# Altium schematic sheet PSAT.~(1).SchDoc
size 381 x 241 mm; SheetNumber: 1; SheetTotal: 2
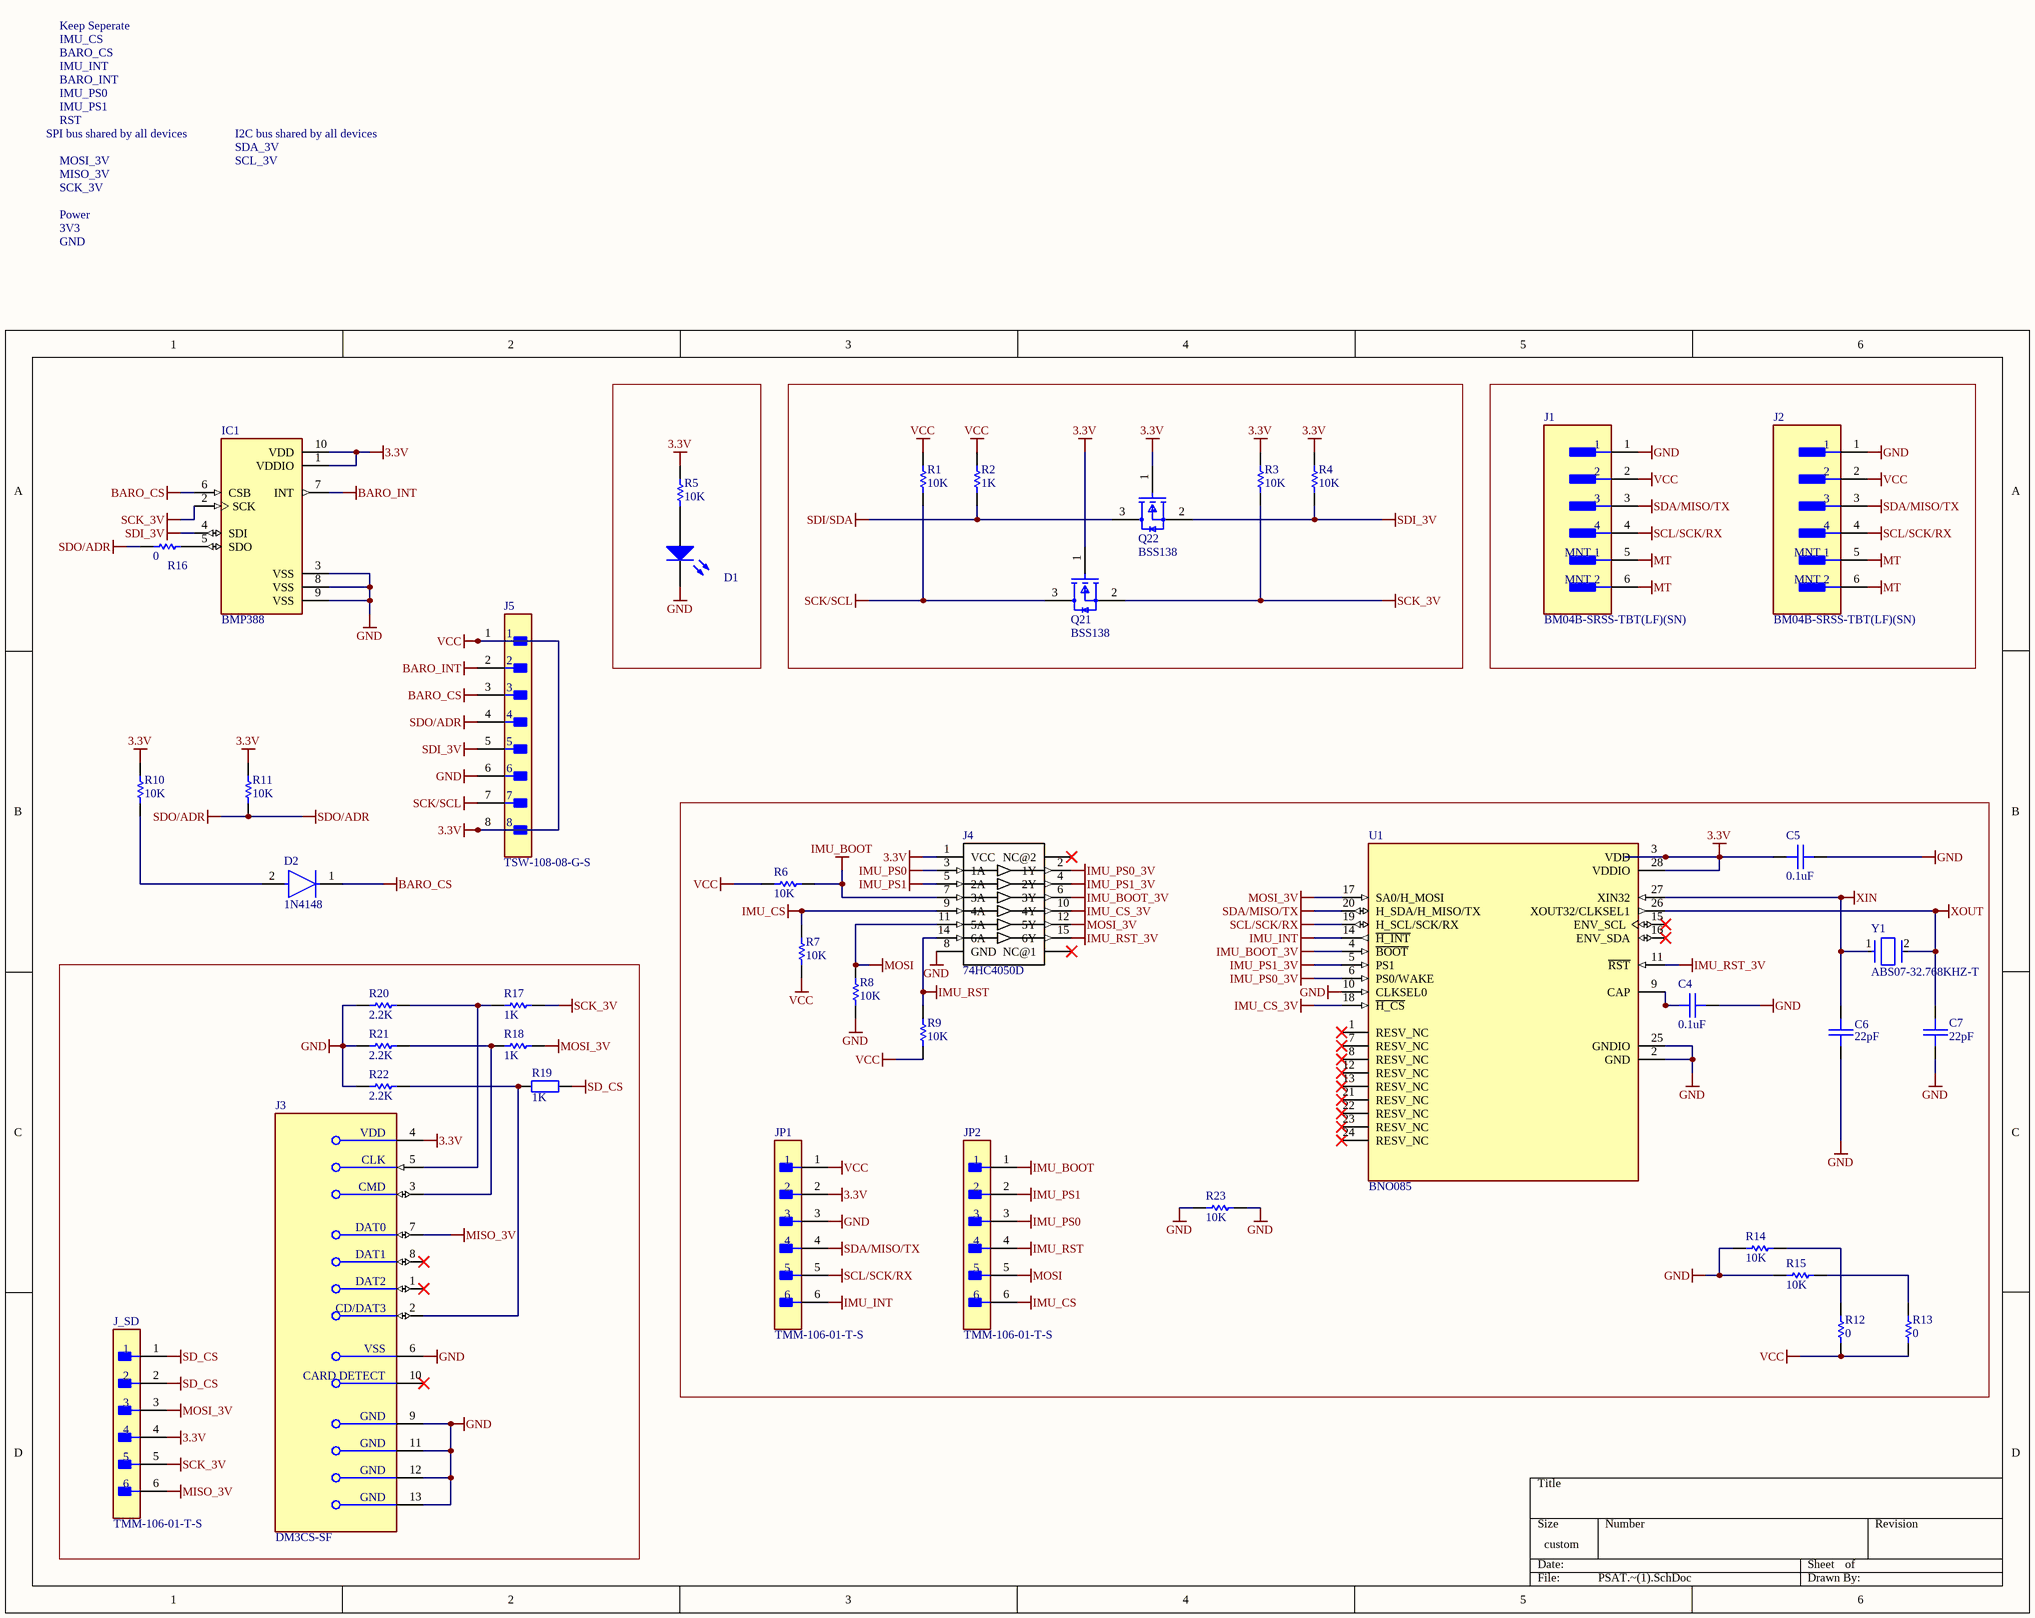
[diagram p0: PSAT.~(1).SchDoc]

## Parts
C4  0.1uF  [0805 CAP]
C5  0.1uF  [0805 CAP]
C6  22pF  [0805 CAP]
C7  22pF  [0805 CAP]
D1  *  [ECE-LED2012-0805SM]  (value not drawn)
D2  1N4148  [FP-017AG-MFG]
IC1  BMP388  [PQFN50P200X200X80-10N]
J1  BM04B-SRSS-TBT(LF)(SN)  [FP-BM04B-SRSS-TBT_LF_SN-MFG]
J2  BM04B-SRSS-TBT(LF)(SN)  [FP-BM04B-SRSS-TBT_LF_SN-MFG]
J3  DM3CS-SF  [FP-DM3CS-SF-MFG]
J4  74HC4050D  [*SO16]
J5  TSW-108-08-G-S  [FP-TSW-108-08-G-S-MFG]
J_SD  TMM-106-01-T-S  [FP-TMM-106-01-T-S-MFG]
JP1  TMM-106-01-T-S  [FP-TMM-106-01-T-S-MFG]
JP2  TMM-106-01-T-S  [FP-TMM-106-01-T-S-MFG]
Q21  BSS138  [FP-318-08-IPC_B]
Q22  BSS138  [FP-318-08-IPC_B]
R1  value 10K  [0805 RES]  (hidden comment: Resistor)
R2  value 1K  [0805 RES]  (hidden comment: Resistor)
R3  value 10K  [0805 RES]  (hidden comment: Resistor)
R4  value 10K  [0805 RES]  (hidden comment: Resistor)
R5  value 10K  [0805 RES]  (hidden comment: Resistor)
R6  value 10K  [0805 RES]  (hidden comment: Resistor)
R7  value 10K  [0805 RES]  (hidden comment: Resistor)
R8  value 10K  [0805 RES]  (hidden comment: Resistor)
R9  value 10K  [0805 RES]  (hidden comment: Resistor)
R10  value 10K  [0805 RES]  (hidden comment: Resistor)
R11  value 10K  [0805 RES]  (hidden comment: Resistor)
R12  value 0  [0805 RES]  (hidden comment: Resistor)
R13  value 0  [0805 RES]  (hidden comment: Resistor)
R14  value 10K  [0805 RES]  (hidden comment: Resistor)
R15  value 10K  [0805 RES]  (hidden comment: Resistor)
R16  value 0  [0805 RES]  (hidden comment: Resistor)
R17  value 1K  [0805 RES]  (hidden comment: Resistor)
R18  value 1K  [0805 RES]  (hidden comment: Resistor)
R19  1K  [0805 RES]
R20  value 2.2K  [0805 RES]  (hidden comment: Resistor)
R21  value 2.2K  [0805 RES]  (hidden comment: Resistor)
R22  value 2.2K  [0805 RES]  (hidden comment: Resistor)
R23  value 10K  [0805 RES]  (hidden comment: Resistor)
U1  BNO085  [IC_BNO085]
Y1  ABS07-32.768KHZ-T  [FP-ABS07-MFG]

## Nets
3.3V: C5.1 IC1.1(VDDIO) IC1.10(VDD) J1.2 J2.2 J3.4(VDD) J4.1(VCC) J5.1 J5.8 J_SD.4 JP1.1 JP1.2 Q21.1(G) Q22.1(G) R1.2 R2.2 R3.2 R4.2 R5.2 R6.1 R7.2 R9.2 R10.2 R11.2 R12.1 R13.1 U1.3(VDD) U1.28(VDDIO)  [also labelled VCC]
BARO_CS: D2.1(C) IC1.6(CSB) J5.3
BARO_INT: IC1.7(INT) J5.2
GND: C4.2 C5.2 C6.2 C7.2 D1.2(K) IC1.3(VSS) IC1.8(VSS) IC1.9(VSS) J1.1 J2.1 J3.6(VSS) J3.9(GND) J3.11(GND) J3.12(GND) J3.13(GND) J4.8(GND) J5.6 JP1.3 R8.2 R14.2 R15.2 R20.1 R21.1 R22.1 R23.1 R23.2 U1.2(GND) U1.10(CLKSEL0) U1.25(GNDIO)
IMU_BOOT: J4.7(3A) JP2.1 R6.2
IMU_BOOT_3V: J4.6(3Y) U1.4(~{BOOT})
IMU_CS: J4.9(4A) JP2.6 R7.1
IMU_CS_3V: J4.10(4Y) U1.18(~{H_CS})
IMU_INT: JP1.6 U1.14(~{H_INT})
IMU_PS0: J4.3(1A) JP2.3
IMU_PS0_3V: J4.2(1Y) U1.6(PS0/WAKE)
IMU_PS1: J4.5(2A) JP2.2
IMU_PS1_3V: J4.4(2Y) U1.5(PS1)
IMU_RST: J4.14(6A) JP2.4 R9.1
IMU_RST_3V: J4.15(6Y) U1.11(~{RST})
MISO_3V: J3.7(DAT0) J_SD.6
MOSI: J4.11(5A) JP2.5 R8.1
MOSI_3V: J4.12(5Y) J_SD.3 R18.2 U1.17(SA0/H_MOSI)
MT: J1.5(MNT_1) J1.6(MNT_2) J2.5(MNT_1) J2.6(MNT_2)
SCK/SCL: J5.7 Q21.3(D) R1.1
SCK_3V: IC1.2(SCK) J_SD.5 Q21.2(S) R3.1 R17.2
SCL/SCK/RX: J1.4 J2.4 JP1.5 U1.19(H_SCL/SCK/RX)
SD_CS: J_SD.1 J_SD.2 R19.2
SDA/MISO/TX: J1.3 J2.3 JP1.4 U1.20(H_SDA/H_MISO/TX)
SDI/SDA: Q22.3(D) R2.1
SDI_3V: IC1.4(SDI) J5.5 Q22.2(S) R4.1
SDO/ADR: J5.4 R11.1 R16.2
XIN: C6.1 U1.27(XIN32) Y1.1
XOUT: C7.1 U1.26(XOUT32/CLKSEL1) Y1.2
NetC4_1: C4.1 U1.9(CAP)
NetD1_1: D1.1(A) R5.1
NetD2_2: D2.2(A) R10.1
NetIC1_5: IC1.5(SDO) R16.1
NetJ3_2: J3.2(CD/DAT3) R19.1 R22.2
NetJ3_3: J3.3(CMD) R18.1 R21.2
NetJ3_5: J3.5(CLK) R17.1 R20.2
NetR12_2: R12.2 R14.1
NetR13_2: R13.2 R15.1

Not connected (* = marked no-connect by the designer): J3 1(DAT2)* 8(DAT1)* 10(CARD_DETECT)*; J4 13(NC@1)* 16(NC@2)*; U1 1(RESV_NC)* 7(RESV_NC)* 8(RESV_NC)* 12(RESV_NC)* 13(RESV_NC)* 15(ENV_SCL)* 16(ENV_SDA)* 21(RESV_NC)* 22(RESV_NC)* 23(RESV_NC)* 24(RESV_NC)*

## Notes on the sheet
- Keep Seperate
- IMU_CS
- BARO_CS
- IMU_INT
- BARO_INT
- SPI bus shared by all devices
- IMU_PS0
- IMU_PS1
- RST
- I2C bus shared by all devices
- SDA_3V
- Power
- MOSI_3V
- MISO_3V
- SCK_3V
- SCL_3V
- 3V3
- GND

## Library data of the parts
C4-C7 = CerCap_SMT_0805: SMT ceramic capacitor 0805 size
D1 = LED-SM0805: SMT LED; Manufacturer: Generic Components; Class I: Optoelectronic
D2 = CMP-07163-000046-1: DIODE GEN PURP 100V 200MA DO35; Forward Voltage: 1V; Max Power Dissipation: 500mW; Max Reverse Current: 5uA; Forward Current: 300mA; Current: 4A; Reverse Recovery Time: 4ns; Element Configuration: Single; Outside Diameter: 1.85mm; Capacitance: 4pF; Polarity: Standard; Max Forward Surge Current (Ifsm): 1A
IC1 = BMP388: P-Sensor SPI I2C 1, 25 Bar SMD
J1 J2 = CMP-17439-000370-1: CONN HEADER SMD 4POS 1MM; Voltage Rating: 50V; Number of Positions: 4; Pitch: 0.039inch; Mated Stacking Heights: 4.9mm
J3 = CMP-11597-000003-1: CONN MICRO SD CARD HINGED TYPE; Pitch: 1.1mm; Connector Type: Connector; Current Rating: 500mA; Voltage Rating (AC): 125V; Gender: Female; Insulation Resistance: 1GR; Number of Positions: 8; Contact Resistance: 100mR
J5 = CMP-02766-000001-1: CONN HEADER VERT 8POS 2.54MM; Manufacturer: Samtec; Number Of Contacts: 8; Conn Orientation: Straight; Conn Gender: Male
J_SD JP1 JP2 = CMP-02766-001694-1: CONN HEADER VERT 6POS 2MM; Gender: Male; Max Voltage Rating (AC): 500V; Number of Contacts: 6; Connector Type: Male Pin
Q21 Q22 = CMP-07173-000101-1: MOSFET N-CH 50V 220MA SOT-23; Turn-Off Delay Time: 20ns; Element Configuration: Single; Rds On Max: 3.5R; Gate to Source Voltage (Vgs): 20V; Threshold Voltage: 1.3V; Number of Elements: 1; Power Dissipation: 360mW; Rise Time: 9ns; Turn-On Delay Time: 2.5ns; Input Capacitance: 27pF; On-State Resistance: 6R
R1-R11 R14 R15 R17 R18 R20-R23 = Resistor: TC1: 0; SimulationGenericComponent: True
R12 R13 R16 = Resistor: SimulationGenericComponent: True
R19 = Res_SMT_0805: 0805 resistor
U1 = BNO085: Accelerometer, Gyroscope, Magnetometer, 9 Axis Sensor IÂ²C, SPI, UART Output; MF: Hillcrest Laboratories,
Y1 = CMP-0447-00001-4: Crystal 32.768kHz ±20ppm (Tol) 12.5pF FUND 70kΩ 2-Pin CSMD T/R; ESR (Equivalent Series Resistance): 70kR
